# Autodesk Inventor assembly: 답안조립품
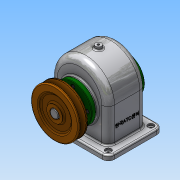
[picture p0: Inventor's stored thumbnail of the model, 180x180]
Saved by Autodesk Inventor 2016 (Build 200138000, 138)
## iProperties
Created: 2018-08
Part Number: 답안조립품
Material: 일반
Document SubType Name: Assembly
Designer: Administrator
Author: Administrator
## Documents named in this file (14)
- C:\Users\Administrator\Desktop\480811V1990\답안조립품.iam
- C:\Users\Administrator\Desktop\480811V1990\본체.ipt
- C:\Users\Administrator\Desktop\480811V1990\축.ipt
- C:\Users\Administrator\Desktop\480811V1990\키 5x5x18.ipt
- C:\Users\Administrator\Desktop\480811V1990\베어링 6203.ipt
- C:\Users\Administrator\Desktop\480811V1990\볼트 M4.ipt
- C:\Users\Administrator\Desktop\480811V1990\뒤커버.ipt
- C:\Users\Administrator\Desktop\480811V1990\키 6x6x22.ipt
- C:\Users\Administrator\Desktop\480811V1990\스퍼기어.ipt
- C:\Users\Administrator\Desktop\480811V1990\앞커버.ipt
- C:\Users\Administrator\Desktop\480811V1990\부시.ipt
- C:\Users\Administrator\Desktop\480811V1990\오일 실 28 40 8.ipt
- C:\Users\Administrator\Desktop\480811V1990\V-벨트풀리.ipt
- C:\Users\Administrator\Desktop\480811V1990\멈춤나사 M4.ipt
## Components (1 placed, 1 different names)
1. V-벨트풀리:1
